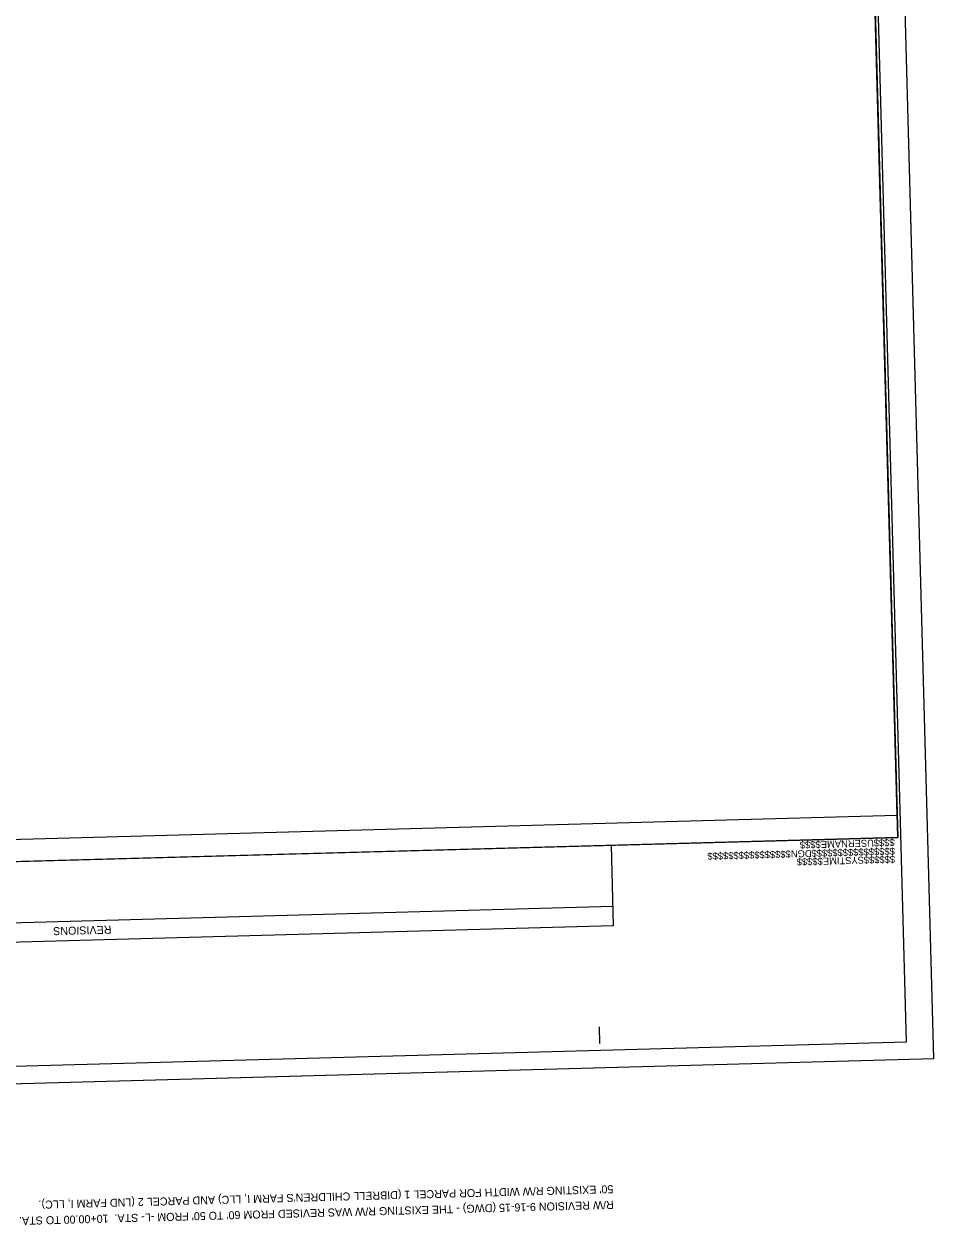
# Model space of a CAD drawing. Extents: x 1835283 to 1836442, y 993567 to 997230.
# Drawn here: x 1835760 to 1836442, y 993567 to 994475 of the extents above; entities that cross this region are included whole.
import ezdxf

# ---------------------------------------------------------------- set-up
doc = ezdxf.new("R2010")
doc.units = 0
for name, color, linetype in [('Sheet Block Revision CELL', 7, 'Continuous'), ('Sheet Clip Boundary CELL', 7, 'Continuous'), ('Sheet Cutting Line CELL', 7, 'Continuous'), ('Sheet Layout Plan Border', 7, 'Continuous'), ('Sheet Plan CELL', 7, 'Continuous'), ('Sheet Plan Layout CELL', 7, 'Continuous'), ('Sheet Plot Border Inside CELL', 7, 'Continuous'), ('Sheet Plot Border Outside CELL', 7, 'Continuous')]:
    doc.layers.add(name, color=color, linetype=linetype)

msp = doc.modelspace()

# ---------------------------------------------------------------- linework, layer by layer
at = {"layer": 'Sheet Block Revision CELL'}
msp.add_line((1836201.04, 993812.95), (1835410.7, 993791.35), dxfattribs=at)
msp.add_lwpolyline([(1836201.46, 993798.4), (1835411.11, 993776.82), (1835409.43, 993837.33), (1836199.78, 993858.92)], close=True, dxfattribs=at)
at = {"layer": 'Sheet Clip Boundary CELL'}
msp.add_lwpolyline([(1836414.25, 993881.51), (1836374.18, 995348.6), (1835535.98, 995325.71), (1835542.09, 995102.18), (1835330.68, 995096.4), (1835364.64, 993852.84)], close=True, dxfattribs=at)
msp.add_lwpolyline([(1836414.25, 993881.51), (1836374.18, 995348.6), (1835535.98, 995325.71), (1835542.09, 995102.18), (1835330.68, 995096.4), (1835364.64, 993852.84)], close=True, dxfattribs=at)
at = {"layer": 'Sheet Cutting Line CELL'}
for p, q in [((1836441.75, 993698.96), (1836395.79, 995381.84)), ((1835347.16, 993669.07), (1836441.75, 993698.96))]:
    msp.add_line(p, q, dxfattribs=at)
at = {"layer": 'Sheet Layout Plan Border'}
msp.add_lwpolyline([(1836414.25, 993881.51), (1836374.18, 995348.6), (1835535.98, 995325.71), (1835542.09, 995102.18), (1835330.68, 995096.4), (1835364.64, 993852.84)], close=True, dxfattribs=at)
msp.add_lwpolyline([(1836414.25, 993881.51), (1836374.18, 995348.6), (1835535.98, 995325.71), (1835542.09, 995102.18), (1835330.68, 995096.4), (1835364.64, 993852.84)], close=True, dxfattribs=at)
at = {"layer": 'Sheet Plan CELL'}
for p, q in [((1836414.7, 993864.77), (1836414.7, 993864.77)), ((1836191.35, 993710.15), (1836191.03, 993722.64))]:
    msp.add_line(p, q, dxfattribs=at)
for points in [[(1835324.15, 995335.59), (1835365.1, 993836.11), (1836414.7, 993864.77), (1836373.75, 995364.23)], [(1836414.7, 993864.77), (1835365.12, 993836.09), (1835329.59, 995135.59), (1835479.6, 995139.7), (1835474.15, 995339.66), (1836373.75, 995364.23)]]:
    msp.add_lwpolyline(points, close=True, dxfattribs=at)
at = {"layer": 'Sheet Plan Layout CELL'}
msp.add_lwpolyline([(1835365.12, 993836.1), (1836414.7, 993864.79), (1836373.75, 995364.23), (1835535.55, 995341.34), (1835542.09, 995102.18), (1835330.68, 995096.4)], close=True, dxfattribs=at)
at = {"layer": 'Sheet Plot Border Inside CELL'}
msp.add_lwpolyline([(1836421.41, 993711.41), (1836375.91, 995376.78), (1835321.32, 995347.99), (1835366.8, 993682.61)], close=True, dxfattribs=at)
at = {"layer": 'Sheet Plot Border Outside CELL'}
msp.add_lwpolyline([(1836441.75, 993698.96), (1836395.79, 995381.84), (1835301.2, 995351.94), (1835347.16, 993669.07)], close=True, dxfattribs=at)

# ---------------------------------------------------------------- texts
at = {"layer": 'Sheet Block Revision CELL'}
for s, p in [('REVISIONS', (1835825.14, 993798.63)), ("50' EXISTING R/W WIDTH FOR PARCEL 1 (DIBRELL CHILDREN'S FARM I, LLC) AND PARCEL 2 (LND FARM I, LLC).", (1836201.4, 993604)), ("R/W REVISION 9-16-15 (DWG) - THE EXISTING R/W WAS REVISED FROM 60' TO 50' FROM -L- STA.  10+00.00 TO STA. 16+81.00 LT./RT.   THE EASEMENTS WERE ADJUSTED TO THE ", (1836201.72, 993592.26))]:
    msp.add_text(s, height=6, rotation=181.56434, dxfattribs=at).set_placement(p)
at = {"layer": 'Sheet Plan CELL'}
for s, p in [('$$$$$$$$$$$$$$$$DGN$$$$$$$$$$$$$$$$', (1836412.55, 993857.08)), ('$$$$USERNAME$$$$', (1836412.36, 993863.62)), ('$$$$$$SYSTIME$$$$$', (1836412.74, 993851))]:
    msp.add_text(s, height=5.25, rotation=181.56434, dxfattribs=at).set_placement(p)

doc.saveas('drawing.dxf')
